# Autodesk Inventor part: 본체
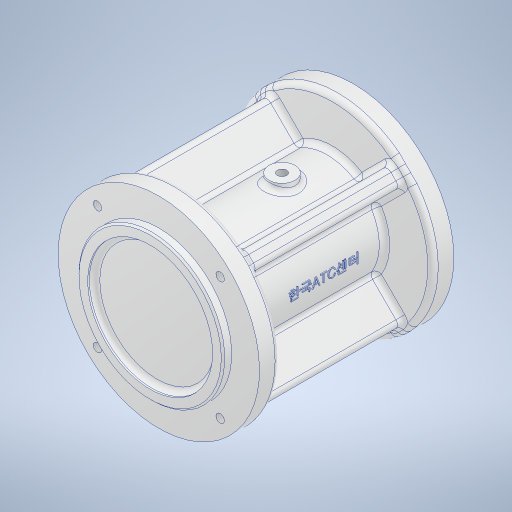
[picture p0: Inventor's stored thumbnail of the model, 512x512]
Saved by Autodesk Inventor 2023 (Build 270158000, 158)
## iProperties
Created: 2024-10
Part Number: 본체
Material: 알루미늄 6061
Document SubType Name: Modeling
Designer: home
Density: 2.7 g/cm^3
Appearance: 알루미늄 - 평지
Mass: 1168.05 g
Surface Area: 973.503 cm^2
Volume: 432.611 cm^3
Author: home
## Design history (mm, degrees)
sketch "스케치2"
  geometry: L1 (0, 75)-(0, -75); L2 (10.5, 64)-(10.5, 61); L3 (10.5, 61)-(16, 61); L4 (16, 61)-(16, 57); L5 (16, 57)-(18, 57); L6 (18, 57)-(18, 39); L7 (18, 39)-(21, 39); L8 (21, 39)-(21, 27); L9 (21, 27)-(30, 27); L10 (30, 27)-(30, -27); L11 (30, -27)-(21, -27); L12 (21, -27)-(21, -43); L13 (10.5, 64)-(0, 64); L14 (21, -43)-(36, -43); L15 (36, -43)-(36, -46); L16 (36, -46)-(0, -46); 8 further points
  constraints: 32 end point, 11 perpendicular, 7 midpoint, 3 vertical, 2 horizontal, 2 point on line, 1 coincident, 1 horizontal alignment
  dimensions: "d0" = 21 diameter of point (10.5, 62.5) L1; "d1" = 3 distance between parallel lines of L3 L13; "d2" = 32 diameter of point (16, 59) L1; "d3" = 4 distance of L3.end L4.end; "d5" = 36 diameter of L6 L1; "d6" = 18 distance of L5.end L6.end; "d7" = 42 diameter of L8 L1; "d9" = 42 diameter of L12 L1; "d11" = 150 distance of L1.start L1.end; "d12" = 72 diameter of point (36, -44.5) L1; "d14" = 3 distance of L14.end L15.end; "d15" = 16 distance of L11.end L12.end; "d32" = 54 distance of L9.end L10.end; "d33" = 60 diameter of L10 L1; "d34" = 82 distance from line of L14 point (19.5, 39)
revolve "회전1" sketch "스케치2" stored, may be unused: angle "d20" = 90 deg
sketch "스케치3"
  geometry: L1 (0, 95.391)-(0, -95.391); L2 (0, 76)-(42, 76); L3 (42, 76)-(42, 71); L4 (42, 71)-(58, 71); L5 (58, 71)-(58, 59); L6 (58, 59)-(23, 59); L7 (23, 59)-(23, 44); L8 (0, -46)-(42, -46); L9 (42, -46)-(42, -41); L10 (42, -41)-(58, -41); L11 (58, -41)-(58, -29); L12 (-36, -46)-(36, -46) reference; L13 (23, 44)-(27, 44); L14 (30, 41)-(30, -29); L15 (30, -29)-(58, -29); A1 r 3 centre (27, 41) between (30, 41) and (27, 44); 7 further points
  constraints: 28 end point, 10 perpendicular, 5 midpoint, 4 point on line, 3 horizontal, 2 point on circle, 2 tangent, 1 centre point, 1 coincident, 1 horizontal alignment, 1 vertical
  dimensions: "d21" = 5 distance of L2.end L3.end; "d22" = 12 distance of L4.end L5.end; "d23" = 122 distance between parallel lines of L8 L2; "d24" = 12 distance of L10.end L11.end; "d25" = 5 distance of L8.end L9.end; "d26" = 116 diameter of point (58, 65) L1; "d27" = 84 diameter of point (42, 73.5) L1; "d28" = 116 diameter of point (58, -35) L1; "d29" = 84 diameter of L9 L1; "d30" = 46 diameter of L7 L1; "d112" = 60 diameter of L14 L1; "d113" = 15 distance from line of point (25, 44) L6; "d114" = 141.39081 distance from line of L1.start L12; "d159" = 3 radius of A1 (derived)
revolve "회전2" sketch "스케치3" stored, may be unused: angle "d35" = 360 deg
sketch "스케치4"
  geometry: C1 r 36 at (0, 0); 1 further point
  constraints: 1 centre point, 1 coincident
  dimensions: "d36" = 72 diameter of C1
extrude "돌출1" cut sketch "스케치4" distance "d37" = 4; taper "d38" = 0 deg
sketch "스케치5"
  geometry: L1 (0, 75)-(0, -75); L2 (10.5, 64)-(10.5, 61); L3 (10.5, 61)-(15.4, 61); L4 (16, 60.4)-(16, 57); L5 (16, 57)-(18, 57); L6 (18, 57)-(18, 39); L7 (18, 39)-(20.4, 39); L8 (21, 38.4)-(21, 27); L9 (21, 27)-(25, 27); L10 (25, 27)-(25, -27); L11 (25, -27)-(21, -27); L12 (21, -27)-(21, -43); L13 (10.5, 64)-(0, 64); L14 (21, -43)-(36, -43); L15 (36, -43)-(36, -46); L16 (36, -46)-(0, -46); L17 (-42, -46)-(42, -46) reference; A1 r 0.6 centre (15.4, 60.4) between (16, 60.4) and (15.4, 61); A2 r 0.6 centre (20.4, 38.4) between (21, 38.4) and (20.4, 39); 11 further points
  constraints: 32 end point, 11 perpendicular, 7 midpoint, 6 point on line, 4 point on circle, 4 tangent, 3 vertical, 2 centre point, 2 coincident, 2 horizontal, 2 horizontal alignment, 1 equal radius
  dimensions: "d39" = 21 diameter of point (10.5, 62.5) L1; "d40" = 3 distance between parallel lines of L3 L13; "d41" = 32 diameter of point (16, 58.7) L1; "d42" = 4 distance of point (16, 61) L4.end; "d43" = 36 diameter of L6 L1; "d44" = 18 distance of L5.end L6.end; "d45" = 42 diameter of L8 L1; "d46" = 42 diameter of L12 L1; "d47" = 150 distance of L1.start L1.end; "d48" = 72 diameter of point (36, -44.5) L1; "d49" = 3 distance of L14.end L15.end; "d50" = 16 distance of L11.end L12.end; "d51" = 54 distance of L9.end L10.end; "d52" = 50 diameter of L10 L1; "d53" = 82 distance from line of L14 point (19.2, 39); "d147" = 0.6 radius of A1
revolve "회전3" sketch "스케치5" stored, may be unused: angle "d54" = 360 deg
sketch "스케치7" dims "d55" = 100
  geometry: L1 (0, 0)-(-66.422, 66.422); L2 (0, 0)-(-78.662, 0); C1 r 58 at (0, 0) reference; C2 r 42 at (0, 0) reference; C3 r 36 at (0, 0) reference; C4 r 23 at (0, 0) reference; 2 further points
  constraints: 4 end point, 1 coincident, 1 horizontal, 1 point on line, 3 other
  dimensions: "d79" = 45 deg angle of L2 L1
  node "투영된 루프1"
sketch "스케치8" dims "d66" = 100
  geometry: L1 (0, 0)-(83.546, 0); L2 (0, 0)-(61.692, 61.692); C1 r 10.5 at (0, 0) reference; C2 r 42 at (0, 0) reference; 2 further points
  constraints: 4 end point, 1 coincident, 1 horizontal, 1 point on line, 3 other
  dimensions: "d90" = 45 deg angle of L1 L2
hole "구멍3" sketch "스케치7" diameter "d80" = 4.917; stored, may be unused: countersink angle "d84" = 90 deg, drill point angle "d86" = 118 deg; dims "d81" = 12, "d82" = 4, "d83" = 2, "d85" = 14
hole "구멍4" sketch "스케치8" diameter "d91" = 4.917; stored, may be unused: countersink angle "d95" = 90 deg, drill point angle "d97" = 118 deg; dims "d92" = 12, "d93" = 4, "d94" = 2, "d96" = 14
sketch "스케치9" dims "d101" = 56
  geometry: C1 r 21 at (0, 0) reference; C2 r 36 at (0, 0) reference; 2 further points
  constraints: 2 vertical alignment, 1 coincident, 2 other
hole "구멍5" sketch "스케치9" at (0, 28) diameter "d102" = 4.134; stored, may be unused: countersink angle "d106" = 90 deg, drill point angle "d108" = 118 deg; dims "d103" = 10, "d104" = 4, "d105" = 2, "d107" = 12
node "작업 평면1"
sketch "스케치10"
  geometry: C1 r 7.5 at (0, 0); 1 further point
  constraints: 1 centre point, 1 coincident
  dimensions: "d117" = 15 diameter of C1
extrude "돌출2" join sketch "스케치10" stored distance "d118" = 4; taper "d119" = 0 deg
node "작업 평면2"
sketch "스케치11"
  geometry: C1 r 7.5 at (0, 0); 1 further point
  constraints: 1 centre point, 1 coincident
  dimensions: "d121" = 15 diameter of C1
extrude "돌출3" join sketch "스케치11" stored distance "d122" = 10; taper "d123" = 0 deg
sketch "스케치12"
  geometry: C1 r 7.5 at (0, 0) reference; 1 further point
  constraints: 1 coincident
hole "구멍6" sketch "스케치12" at (0, 0) diameter "d124" = 5.45873; stored, may be unused: countersink angle "d128" = 90 deg, drill point angle "d130" = 118 deg; dims "d125" = 12, "d126" = 4, "d127" = 2, "d129" = 8
node "작업 평면3"
sketch "스케치13"
  geometry: L1 (-59, 54)-(29, 54); L2 (-59, -58)-(-59, 58) reference; L3 (-59, 54)-(-59, 23); L4 (29, 54)-(29, 30); 3 further points
  constraints: 6 end point, 1 horizontal, 1 parallel
  dimensions: "d131" = 54 distance from line of point (0, 0) L1; "d132" = 90 deg angle of L3 L1
feature "리브1" sketch "스케치13" dims "d133" = 1, "d134" = 10, "d135" = 0, "d136" = 0, "d137" = 1, "d138" = 1
chamfer "모따기1" distance "d139" = 1; stored, may be unused: second distance "d140" = 2, angle "d141" = 45 deg
fillet "모깎기1" dims "d142" = 3
fillet "모깎기2" dims "d143" = 3
fillet "모깎기3" dims "d144" = 3
fillet "모깎기4" dims "d145" = 3
fillet "모깎기5" dims "d146" = 3
fillet "모깎기6" dims "d148" = 3
fillet "모깎기7" dims "d149" = 3
chamfer "모따기2" distance "d150" = 1; stored, may be unused: second distance "d151" = 2, angle "d152" = 45 deg
fillet "모깎기8" dims "d153" = 3
node "작업 평면4"
sketch "스케치15"
  geometry: L1 (41, -46)-(-41, -46) reference; 2 further points
  constraints: 1 vertical alignment, 1 other
  dimensions: "d155" = 52 distance from line of L1 point (0, 6)
feature "엠보싱1" sketch "스케치15" dims "d0" = 21, "d1" = 3, "d2" = 32, "d3" = 4, "d5" = 36, "d6" = 18, "d7" = 42, "d9" = 42, "d11" = 150, "d12" = 72, "d14" = 3, "d15" = 16, "d32" = 54, "d33" = 60, "d34" = 82, "d156" = 0.5, "d157" = 0
fillet "모깎기9" dims "d158" = 3
node "솔리드1"
pattern_circular "원형 패턴3" dims angle "d88" = 360 deg
pattern_circular "원형 패턴4" dims angle "d99" = 360 deg
pattern_circular "원형 패턴5" dims angle "d110" = 360 deg
mirror "미러1"
mirror "미러2"
feature "A9D066F2-1C7D-4E18-AEED-F7BC21143FA4" dims "d80" = 4.917, "d81" = 12, "d82" = 4, "d83" = 2, "d84" = 90 deg, "d85" = 14, "d86" = 118 deg
other parameters: "d116" = 34, "d120" = -34
